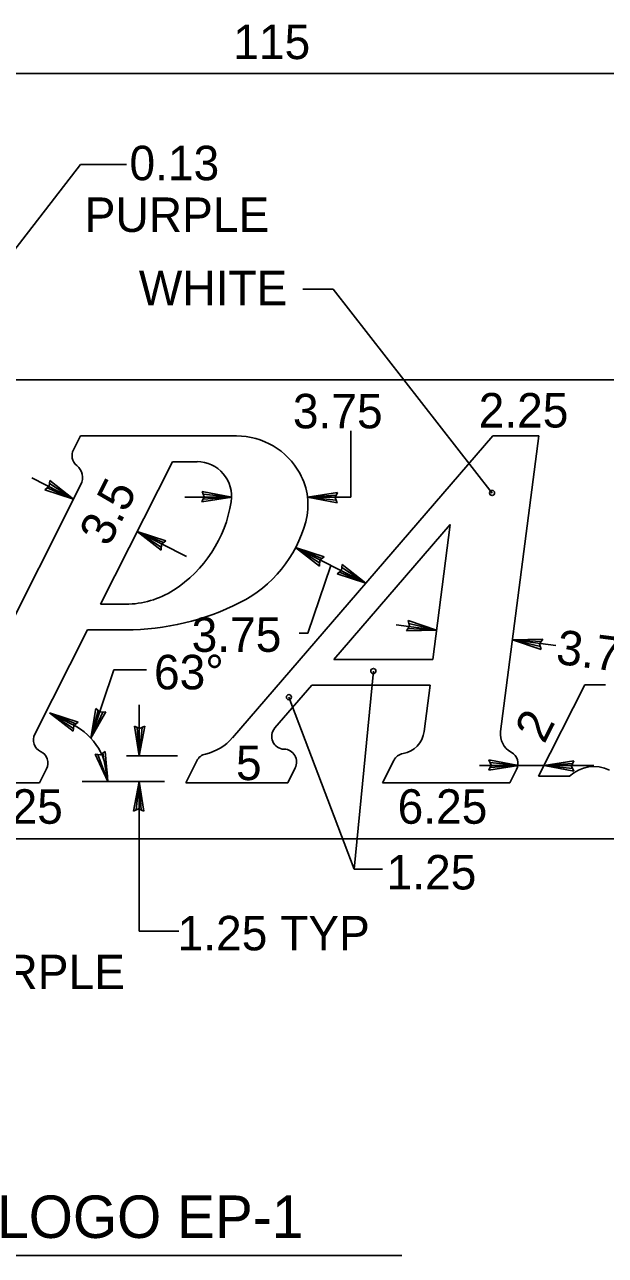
# Model space of a CAD drawing. Extents: x 10268197 to 10269179, y 2141503 to 2142677.
# Drawn here: x 10268620.55 to 10268632.35, y 2142243.22 to 2142268.21 of the extents above; entities that cross this region are included whole.
import ezdxf

# ---------------------------------------------------------------- set-up
doc = ezdxf.new("R2010")
doc.units = 0
for name, color, linetype in [('1', 7, 'Continuous'), ('2', 7, 'Continuous'), ('21', 7, 'Continuous')]:
    doc.layers.add(name, color=color, linetype=linetype)

msp = doc.modelspace()

# ---------------------------------------------------------------- linework, layer by layer
at = {"layer": '1'}
for p, q in [((10268601.85, 2142267.213), (10268627.004, 2142267.213)), ((10268627.004, 2142267.213), (10268649.465, 2142267.213)), ((10268619.662, 2142262.748), (10268621.688, 2142265.366)), ((10268621.688, 2142265.366), (10268622.624, 2142265.366)), ((10268626.201, 2142262.839), (10268626.817, 2142262.839)), ((10268626.817, 2142262.839), (10268630.045, 2142258.699)), ((10268627.18, 2142258.615), (10268627.18, 2142259.959)), ((10268620.702, 2142259.008), (10268621.547, 2142258.577)), ((10268621.055, 2142258.839), (10268620.965, 2142258.766)), ((10268621.547, 2142258.577), (10268621.013, 2142258.804)), ((10268621.064, 2142258.954), (10268621.055, 2142258.839)), ((10268621.547, 2142258.577), (10268621.059, 2142258.894)), ((10268621.547, 2142258.577), (10268621.064, 2142258.954)), ((10268621.547, 2142258.577), (10268620.965, 2142258.766)), ((10268623.808, 2142258.615), (10268624.759, 2142258.615)), ((10268624.201, 2142258.624), (10268624.153, 2142258.519)), ((10268624.759, 2142258.615), (10268624.153, 2142258.519)), ((10268624.759, 2142258.615), (10268624.157, 2142258.732)), ((10268624.157, 2142258.732), (10268624.201, 2142258.624)), ((10268624.759, 2142258.615), (10268624.178, 2142258.574)), ((10268624.759, 2142258.615), (10268624.181, 2142258.675)), ((10268626.299, 2142258.615), (10268626.905, 2142258.71)), ((10268626.299, 2142258.615), (10268626.879, 2142258.655)), ((10268626.299, 2142258.615), (10268627.18, 2142258.615)), ((10268626.299, 2142258.615), (10268626.901, 2142258.498)), ((10268626.299, 2142258.615), (10268626.878, 2142258.554)), ((10268626.857, 2142258.605), (10268626.905, 2142258.71)), ((10268626.901, 2142258.498), (10268626.857, 2142258.605)), ((10268622.841, 2142257.919), (10268623.838, 2142257.411)), ((10268622.841, 2142257.919), (10268623.424, 2142257.73)), ((10268622.841, 2142257.919), (10268623.324, 2142257.542)), ((10268622.841, 2142257.919), (10268623.329, 2142257.603)), ((10268622.841, 2142257.919), (10268623.376, 2142257.692)), ((10268623.324, 2142257.542), (10268623.333, 2142257.658)), ((10268623.333, 2142257.658), (10268623.424, 2142257.73)), ((10268626.054, 2142257.595), (10268627.482, 2142256.867)), ((10268626.054, 2142257.595), (10268626.637, 2142257.405)), ((10268626.054, 2142257.595), (10268626.538, 2142257.217)), ((10268626.054, 2142257.595), (10268626.543, 2142257.279)), ((10268626.054, 2142257.595), (10268626.589, 2142257.368)), ((10268626.538, 2142257.217), (10268626.546, 2142257.334)), ((10268626.546, 2142257.334), (10268626.637, 2142257.405)), ((10268628.919, 2142255.917), (10268628.338, 2142256.11)), ((10268628.338, 2142256.11), (10268628.368, 2142255.998)), ((10268628.919, 2142255.917), (10268628.353, 2142256.052)), ((10268628.919, 2142255.917), (10268628.098, 2142256.024)), ((10268628.368, 2142255.998), (10268628.306, 2142255.9)), ((10268628.919, 2142255.917), (10268628.306, 2142255.9)), ((10268628.919, 2142255.917), (10268628.339, 2142255.952)), ((10268630.459, 2142255.718), (10268631.072, 2142255.735)), ((10268630.459, 2142255.718), (10268631.337, 2142255.604)), ((10268630.459, 2142255.718), (10268631.041, 2142255.524)), ((10268630.459, 2142255.718), (10268631.025, 2142255.584)), ((10268630.459, 2142255.718), (10268631.039, 2142255.683)), ((10268631.011, 2142255.637), (10268631.072, 2142255.735)), ((10268631.041, 2142255.524), (10268631.011, 2142255.637)), ((10268622.366, 2142255.107), (10268621.897, 2142253.723)), ((10268623.031, 2142255.107), (10268622.366, 2142255.107)), ((10268627.248, 2142251.066), (10268627.635, 2142255.085)), ((10268627.248, 2142251.066), (10268625.92, 2142254.555)), ((10268621.897, 2142253.723), (10268622, 2142254.327)), ((10268622.085, 2142254.248), (10268622, 2142254.327)), ((10268622.878, 2142253.361), (10268622.878, 2142254.397)), ((10268621.535, 2142253.996), (10268621.059, 2142254.239)), ((10268621.059, 2142254.239), (10268621.642, 2142254.049)), ((10268621.059, 2142254.239), (10268621.542, 2142253.862)), ((10268621.059, 2142254.239), (10268621.547, 2142253.922)), ((10268621.059, 2142254.239), (10268621.594, 2142254.012)), ((10268621.552, 2142253.978), (10268621.642, 2142254.049)), ((10268621.897, 2142253.723), (10268622.045, 2142254.285)), ((10268621.897, 2142253.723), (10268622.2, 2142254.255)), ((10268621.897, 2142253.723), (10268622.14, 2142254.251)), ((10268622.2, 2142254.255), (10268622.085, 2142254.248)), ((10268621.542, 2142253.862), (10268621.552, 2142253.978)), ((10268622.878, 2142253.361), (10268622.783, 2142253.967)), ((10268622.888, 2142253.919), (10268622.783, 2142253.967)), ((10268622.878, 2142253.361), (10268622.838, 2142253.941)), ((10268622.878, 2142253.361), (10268622.995, 2142253.963)), ((10268622.878, 2142253.361), (10268622.939, 2142253.94)), ((10268622.995, 2142253.963), (10268622.888, 2142253.919)), ((10268622.241, 2142252.844), (10268621.983, 2142253.399)), ((10268622.097, 2142253.382), (10268621.983, 2142253.399)), ((10268622.241, 2142252.844), (10268622.043, 2142253.39)), ((10268622.188, 2142253.454), (10268622.097, 2142253.382)), ((10268622.241, 2142252.844), (10268622.14, 2142253.416)), ((10268622.241, 2142252.844), (10268622.188, 2142253.454)), ((10268623.655, 2142253.361), (10268622.62, 2142253.361)), ((10268630.583, 2142253.166), (10268629.787, 2142253.166)), ((10268631.1, 2142253.166), (10268630.583, 2142253.166)), ((10268632.11, 2142253.166), (10268631.1, 2142253.166)), ((10268623.396, 2142252.844), (10268621.724, 2142252.844)), ((10268622.878, 2142252.844), (10268622.762, 2142252.242)), ((10268622.878, 2142252.844), (10268622.818, 2142252.265)), ((10268622.878, 2142252.844), (10268622.878, 2142249.807)), ((10268622.878, 2142252.844), (10268622.975, 2142252.239)), ((10268622.878, 2142252.844), (10268622.919, 2142252.264)), ((10268622.762, 2142252.242), (10268622.869, 2142252.287)), ((10268622.869, 2142252.287), (10268622.975, 2142252.239)), ((10268627.82, 2142251.066), (10268627.248, 2142251.066)), ((10268622.878, 2142249.807), (10268623.686, 2142249.807))]:
    msp.add_line(p, q, dxfattribs=at)
msp.add_lwpolyline([(10268626.13, 2142255.856), (10268626.305, 2142255.856), (10268626.768, 2142257.231)], dxfattribs=at)
for centre in [(10268630.045, 2142258.7), (10268627.634, 2142255.085), (10268625.92, 2142254.555)]:
    msp.add_circle(centre, 0.0518, dxfattribs=at)
msp.add_arc((10268620.948, 2142252.844), 1.294, 0, 62.9941, dxfattribs=at)
at = {"layer": '2'}
for p, q in [((10268619.941, 2142260.995), (10268649.465, 2142260.995)), ((10268621.687, 2142259.857), (10268621.546, 2142259.579)), ((10268624.857, 2142259.857), (10268621.687, 2142259.857)), ((10268624.777, 2142253.732), (10268630.062, 2142259.857)), ((10268630.062, 2142259.857), (10268630.994, 2142259.857)), ((10268630.994, 2142259.857), (10268630.219, 2142253.857)), ((10268622.093, 2142256.442), (10268623.558, 2142259.335)), ((10268623.558, 2142259.335), (10268624.057, 2142259.335)), ((10268621.696, 2142258.871), (10268619.134, 2142253.804)), ((10268629.196, 2142258.058), (10268626.833, 2142255.32)), ((10268628.842, 2142255.32), (10268629.196, 2142258.058)), ((10268622.606, 2142256.442), (10268622.093, 2142256.442)), ((10268620.76, 2142253.805), (10268621.83, 2142255.92)), ((10268621.83, 2142255.92), (10268622.606, 2142255.92)), ((10268626.833, 2142255.32), (10268628.842, 2142255.32)), ((10268626.385, 2142254.799), (10268625.634, 2142253.93)), ((10268628.789, 2142254.799), (10268626.385, 2142254.799)), ((10268628.667, 2142253.857), (10268628.789, 2142254.799)), ((10268630.99, 2142252.949), (10268631.93, 2142254.807)), ((10268631.93, 2142254.807), (10268632.345, 2142254.807)), ((10268620.859, 2142252.818), (10268621, 2142253.097)), ((10268623.825, 2142252.818), (10268624.05, 2142253.264)), ((10268626.048, 2142253.119), (10268625.895, 2142252.818)), ((10268627.819, 2142252.818), (10268628.047, 2142253.27)), ((10268630.543, 2142253.087), (10268630.407, 2142252.818)), ((10268618.272, 2142252.818), (10268620.859, 2142252.818)), ((10268625.895, 2142252.818), (10268623.825, 2142252.818)), ((10268630.407, 2142252.818), (10268627.819, 2142252.818)), ((10268631.619, 2142252.949), (10268630.99, 2142252.949)), ((10268619.077, 2142251.679), (10268644.718, 2142251.679))]:
    msp.add_line(p, q, dxfattribs=at)
for centre, major_axis, start_param, end_param in [((10268624.857, 2142258.371), (0, 1.486), 5.226065, 6.283185), ((10268621.776, 2142259.46), (0, -0.261), 4.240773, 5.605302), ((10268624.056, 2142258.632), (0, -0.704), 1.415043, 3.141593), ((10268621.419, 2142259.014), (0, -0.313), 1.099604, 2.46371), ((10268625.014, 2142258.461), (0, 1.303), 4.445482, 5.226065), ((10268622.19, 2142258.927), (0, -2.607), 0.565847, 1.415043), ((10268623.766, 2142258.804), (0, -2.607), 0.465011, 1.30389), ((10268622.606, 2142258.267), (0, -1.825), 0, 0.565847), ((10268622.606, 2142261.135), (0, -5.214), 0, 0.465011), ((10268620.99, 2142253.687), (0, 0.261), 1.099355, 2.701477), ((10268625.829, 2142253.759), (0, 0.261), 0.854904, 3.118676), ((10268628.154, 2142253.924), (0, -0.521), 0.161263, 1.440999), ((10268630.629, 2142253.803), (0, 0.417), 1.441439, 2.650585), ((10268623.996, 2142254.417), (0, -1.043), 0.22194, 0.855152), ((10268620.769, 2142253.215), (0, 0.261), 4.241567, 5.84307), ((10268624.281, 2142253.146), (0, -0.261), 3.363532, 4.241567), ((10268625.817, 2142253.238), (0, 0.261), 4.240773, 6.260268), ((10268628.278, 2142253.152), (0, -0.261), 3.302856, 4.241567), ((10268630.312, 2142253.205), (0, 0.261), 4.240773, 5.792177), ((10268632.115, 2142252.416), (0, -0.73), 2.69443, 3.895387)]:
    msp.add_ellipse(centre, major_axis=major_axis, ratio=0.992614, start_param=start_param, end_param=end_param, dxfattribs=at)
at = {"layer": '21'}
for p, q in [((10268626.989, 2142257.129), (10268626.898, 2142257.057)), ((10268627.482, 2142256.867), (10268626.898, 2142257.057)), ((10268627.482, 2142256.867), (10268626.946, 2142257.095)), ((10268626.998, 2142257.245), (10268626.989, 2142257.129)), ((10268627.482, 2142256.867), (10268626.993, 2142257.184)), ((10268627.482, 2142256.867), (10268626.998, 2142257.245)), ((10268630.025, 2142253.176), (10268629.977, 2142253.071)), ((10268630.583, 2142253.166), (10268629.977, 2142253.071)), ((10268630.583, 2142253.166), (10268629.98, 2142253.284)), ((10268629.98, 2142253.284), (10268630.025, 2142253.176)), ((10268630.583, 2142253.166), (10268630.003, 2142253.227)), ((10268630.583, 2142253.166), (10268630.003, 2142253.126)), ((10268631.1, 2142253.166), (10268631.707, 2142253.263)), ((10268631.1, 2142253.166), (10268631.681, 2142253.207)), ((10268631.1, 2142253.166), (10268631.703, 2142253.05)), ((10268631.1, 2142253.166), (10268631.68, 2142253.106)), ((10268631.659, 2142253.157), (10268631.707, 2142253.263)), ((10268631.703, 2142253.05), (10268631.659, 2142253.157)), ((10268618.353, 2142243.223), (10268628.215, 2142243.223))]:
    msp.add_line(p, q, dxfattribs=at)

# ---------------------------------------------------------------- texts
at = {"layer": '1'}
for s, height, p in [('115', 0.7, (10268624.791, 2142267.508)), ('0.13', 0.7, (10268622.683, 2142265.049)), ('PURPLE', 0.7, (10268621.774, 2142263.999)), ('WHITE', 0.7, (10268622.873, 2142262.512)), ('3.75', 0.7, (10268626.001, 2142260.012)), ('2.25', 0.7, (10268629.773, 2142260.029)), ('63°', 0.7, (10268623.181, 2142254.714)), ('5', 0.7, (10268624.845, 2142252.871)), ('6.25', 0.7, (10268619.508, 2142251.985)), ('6.25', 0.7, (10268628.127, 2142251.985)), ('1.25', 0.7, (10268627.904, 2142250.651)), ('1.25 TYP', 0.7, (10268623.66, 2142249.415)), ('PURPLE', 0.7, (10268618.844, 2142248.627)), ('LOGO EP-1', 0.8624, (10268619.996, 2142243.576))]:
    msp.add_text(s, height=height, dxfattribs=at).set_placement(p)
for s, rotation, p in [('3.5', 62.9907, (10268622.257, 2142257.586)), ('3.75', 360, (10268623.945, 2142255.475)), ('3.75', 352.5994, (10268631.323, 2142255.236)), ('2', 63, (10268631.103, 2142253.589))]:
    msp.add_text(s, height=0.7, rotation=rotation, dxfattribs=at).set_placement(p)

doc.saveas('drawing.dxf')
